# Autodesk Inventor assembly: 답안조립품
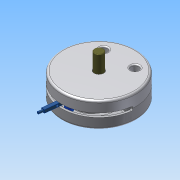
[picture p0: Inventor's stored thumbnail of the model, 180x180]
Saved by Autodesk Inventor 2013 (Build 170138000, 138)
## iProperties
Created: 2015-04
Part Number: 답안조립품
Document SubType Name: Assembly
Designer: Administrator
Author: Administrator
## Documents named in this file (10)
- C:\Users\Administrator\Desktop\450406V1008\답안조립품.iam
- C:\Users\Administrator\Desktop\450406V1008\M 10 x 35.ipt
- C:\Users\Administrator\Desktop\450406V1008\덮개.ipt
- C:\Users\Administrator\Desktop\450406V1008\멈춤링.ipt
- C:\Users\Administrator\Desktop\450406V1008\베어링62_22.ipt
- C:\Users\Administrator\Desktop\450406V1008\본체.ipt
- C:\Users\Administrator\Desktop\450406V1008\슬라이더.ipt
- C:\Users\Administrator\Desktop\450406V1008\슬라이더2.ipt
- C:\Users\Administrator\Desktop\450406V1008\축.ipt
- C:\Users\Administrator\Desktop\450406V1008\평행핀.ipt
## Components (2 placed, 1 different names)
1. M 10 x 35:1
2. M 10 x 35:2
